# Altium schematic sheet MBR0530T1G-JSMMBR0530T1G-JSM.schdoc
size 127 x 101 mm
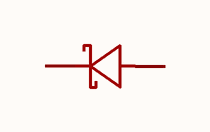
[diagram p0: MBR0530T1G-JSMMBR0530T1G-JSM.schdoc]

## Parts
D?  mbr0530t1g-jsm  [SOD-123_L2.7-W1.6-LS3.6-RD]  (value not drawn)

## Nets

Not connected (* = marked no-connect by the designer): D? 1(K) 2(A)

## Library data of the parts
D? = mbr0530t1g-jsm: 二极管配置:1个独立式;正向压降(Vf):375mV;直流反向耐压(Vr):30V;整流电流:500mA;; Manufacturer: JSMSEMI(杰盛微); AddInBom: yes; ModelId: 4de6fd262b3843a69bdd10ef457c0214; ModelTransform: 141.732,62.992,0,0,0,0,0,0,0; Diode Configuration: 1个独立式; Voltage - Forward(Vf@If): 375mV; Voltage - DC Reverse(Vr): 30V; Current - Rectified: 500mA; Reverse Leakage Current (Ir): 20uA; Operating Junction Temperature Range: -65℃~+125℃; Non-Repetitive Peak Forward Surge Current: 5.5A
